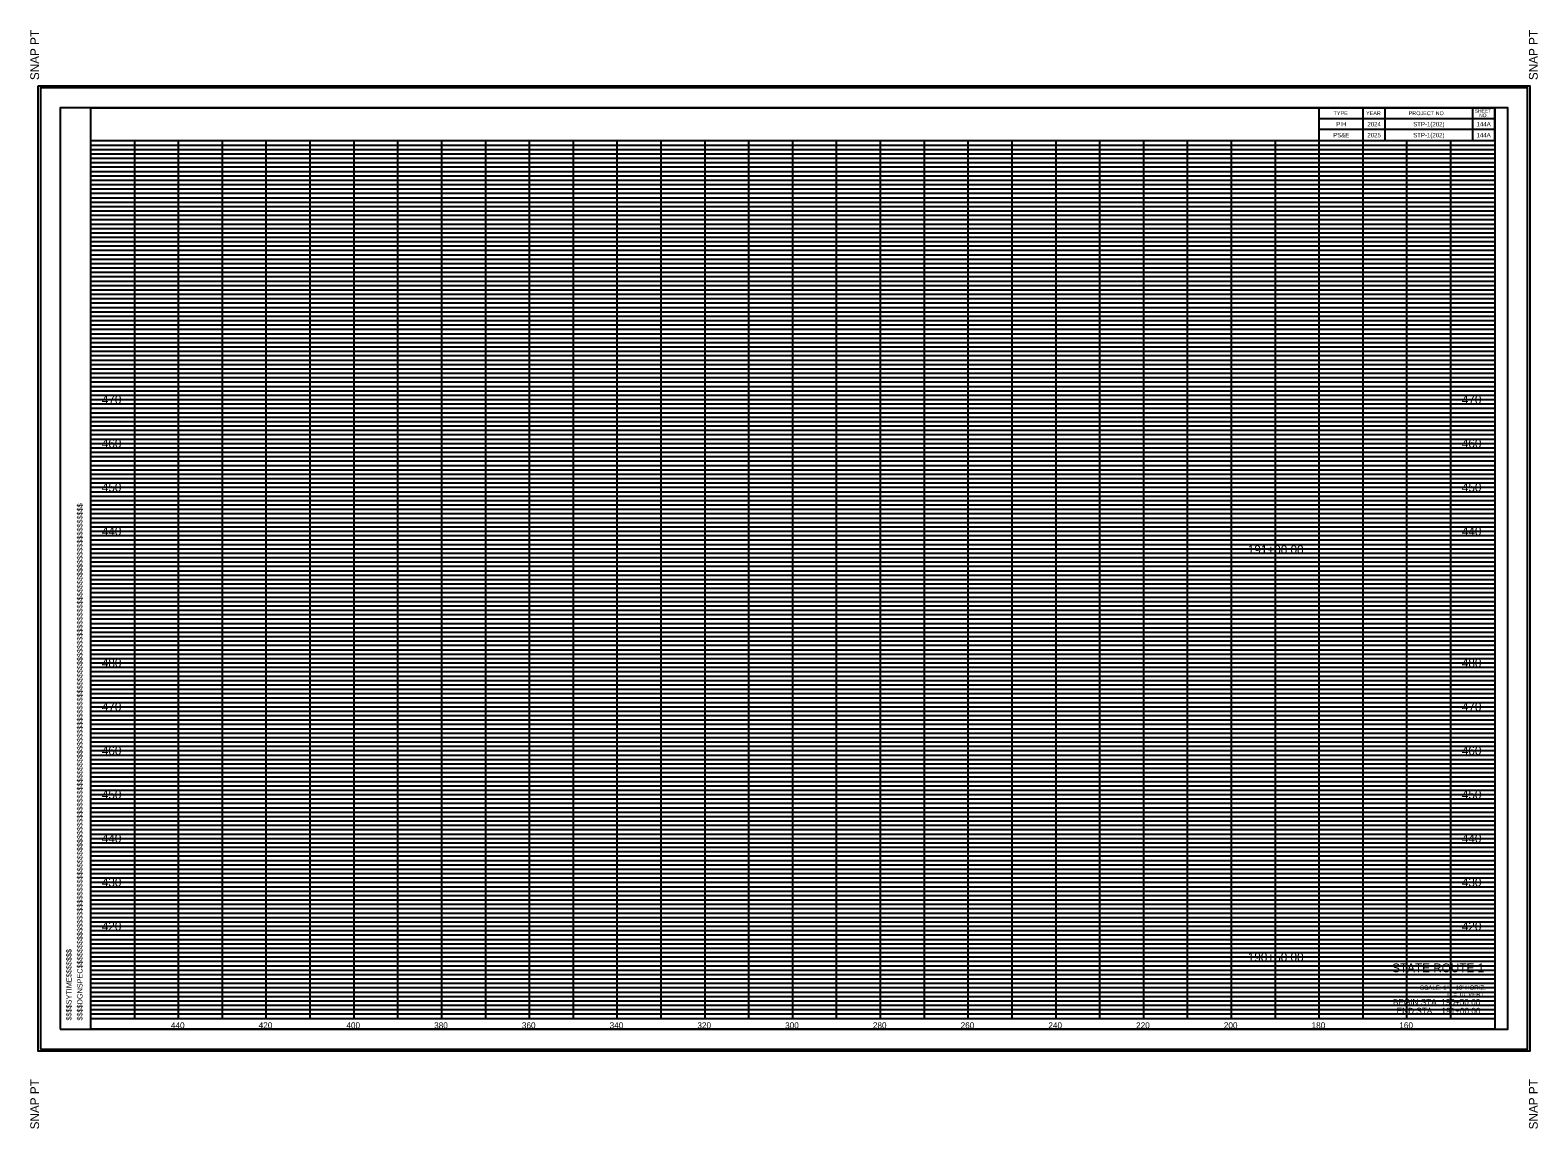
# Model space of a CAD drawing. Extents: x -200 to 23470, y -200 to 2389.
# Drawn here: x 6266.2 to 6609.8, y 1494.8 to 1745.2 of the extents above; entities that cross this region are included whole.
import ezdxf

# ---------------------------------------------------------------- set-up
doc = ezdxf.new("R2010")
doc.units = 0
for name, color, linetype in [('Default', 7, 'Continuous'), ('DESIGN - SCRATCH - User 1', 7, 'Continuous'), ('DESIGN - SHEET - Corner Text', 7, 'Continuous'), ('DESIGN - SHEET - Light Grid', 7, 'Continuous'), ('DESIGN - SHEET - Linework', 7, 'Continuous'), ('DESIGN - SHEET - Plot Shape', 7, 'Continuous'), ('SURVEY - CENTERLINE - Preliminary', 7, 'Continuous')]:
    doc.layers.add(name, color=color, linetype=linetype)

# ---------------------------------------------------------------- blocks, each defined once
blk = doc.blocks.new('XSTSHT')
at = {"layer": 'DESIGN - SCRATCH - User 1'}
for p, q in [((28.5, 20.375), (28.5, 20.375)), ((29.25, 20.375), (29.25, 20.375)), ((30.5, 20.375), (30.5, 20.375)), ((31.75, 20.375), (31.75, 20.375)), ((28.5, 20.125), (28.5, 20.125)), ((29.25, 20.125), (29.25, 20.125)), ((30.5, 20.125), (30.5, 20.125)), ((31.75, 20.125), (31.75, 20.125)), ((0, 0), (0, 0))]:
    blk.add_line(p, q, dxfattribs=at)
at = {"layer": 'DESIGN - SHEET - Light Grid'}
for p, q in [((0, 19.9), (32, 19.9)), ((0, 19.8), (32, 19.8)), ((0, 19.7), (32, 19.7)), ((0, 19.6), (32, 19.6)), ((0, 19.5), (32, 19.5)), ((0, 19.4), (32, 19.4)), ((0, 19.3), (32, 19.3)), ((0, 19.2), (32, 19.2)), ((0, 19.1), (32, 19.1)), ((0, 18.9), (32, 18.9)), ((0, 18.8), (32, 18.8)), ((0, 18.7), (32, 18.7)), ((0, 18.6), (32, 18.6)), ((0, 18.5), (32, 18.5)), ((0, 18.4), (32, 18.4)), ((0, 18.3), (32, 18.3)), ((0, 18.2), (32, 18.2)), ((0, 18.1), (32, 18.1)), ((0, 17.9), (32, 17.9)), ((0, 17.8), (32, 17.8)), ((0, 17.7), (32, 17.7)), ((0, 17.6), (32, 17.6)), ((0, 17.5), (32, 17.5)), ((0, 17.4), (32, 17.4)), ((0, 17.3), (32, 17.3)), ((0, 17.2), (32, 17.2)), ((0, 17.1), (32, 17.1)), ((0, 16.9), (32, 16.9)), ((0, 16.8), (32, 16.8)), ((0, 16.7), (32, 16.7)), ((0, 16.6), (32, 16.6)), ((0, 16.5), (32, 16.5)), ((0, 16.4), (32, 16.4)), ((0, 16.3), (32, 16.3)), ((0, 16.2), (32, 16.2)), ((0, 16.1), (32, 16.1)), ((0, 15.9), (32, 15.9)), ((0, 15.8), (32, 15.8)), ((0, 15.7), (32, 15.7)), ((0, 15.6), (32, 15.6)), ((0, 15.5), (32, 15.5)), ((0, 15.4), (32, 15.4)), ((0, 15.3), (32, 15.3)), ((0, 15.2), (32, 15.2)), ((0, 15.1), (32, 15.1)), ((0, 14.9), (32, 14.9)), ((0, 14.8), (32, 14.8)), ((0, 14.7), (32, 14.7)), ((0, 14.6), (32, 14.6)), ((0, 14.5), (32, 14.5)), ((0, 14.4), (32, 14.4)), ((0, 14.3), (32, 14.3)), ((0, 14.2), (32, 14.2)), ((0, 14.1), (32, 14.1)), ((0, 13.9), (32, 13.9)), ((0, 13.8), (32, 13.8)), ((0, 13.7), (32, 13.7)), ((0, 13.6), (32, 13.6)), ((0, 13.5), (32, 13.5)), ((0, 13.4), (32, 13.4)), ((0, 13.3), (32, 13.3)), ((0, 13.2), (32, 13.2)), ((0, 13.1), (32, 13.1)), ((0, 12.9), (32, 12.9)), ((0, 12.8), (32, 12.8)), ((0, 12.7), (32, 12.7)), ((0, 12.6), (32, 12.6)), ((0, 12.5), (32, 12.5)), ((0, 12.4), (32, 12.4)), ((0, 12.3), (32, 12.3)), ((0, 12.2), (32, 12.2)), ((0, 12.1), (32, 12.1)), ((0, 11.9), (32, 11.9)), ((0, 11.8), (32, 11.8)), ((0, 11.7), (32, 11.7)), ((0, 11.6), (32, 11.6)), ((0, 11.5), (32, 11.5)), ((0, 11.4), (32, 11.4)), ((0, 11.3), (32, 11.3)), ((0, 11.2), (32, 11.2)), ((0, 11.1), (32, 11.1)), ((0, 10.9), (32, 10.9)), ((0, 10.8), (32, 10.8)), ((0, 10.7), (32, 10.7)), ((0, 10.6), (32, 10.6)), ((0, 10.5), (32, 10.5)), ((0, 10.4), (32, 10.4)), ((0, 10.3), (32, 10.3)), ((0, 10.2), (32, 10.2)), ((0, 10.1), (32, 10.1)), ((0, 9.9), (32, 9.9)), ((0, 9.8), (32, 9.8)), ((0, 9.7), (32, 9.7)), ((0, 9.6), (32, 9.6)), ((0, 9.5), (32, 9.5)), ((0, 9.4), (32, 9.4)), ((0, 9.3), (32, 9.3)), ((0, 9.2), (32, 9.2)), ((0, 9.1), (32, 9.1)), ((0, 8.9), (32, 8.9)), ((0, 8.8), (32, 8.8)), ((0, 8.7), (32, 8.7)), ((0, 8.6), (32, 8.6)), ((0, 8.5), (32, 8.5)), ((0, 8.4), (32, 8.4)), ((0, 8.3), (32, 8.3)), ((0, 8.2), (32, 8.2)), ((0, 8.1), (32, 8.1)), ((0, 7.9), (32, 7.9)), ((0, 7.8), (32, 7.8)), ((0, 7.7), (32, 7.7)), ((0, 7.6), (32, 7.6)), ((0, 7.5), (32, 7.5)), ((0, 7.4), (32, 7.4)), ((0, 7.3), (32, 7.3)), ((0, 7.2), (32, 7.2)), ((0, 7.1), (32, 7.1)), ((0, 6.9), (32, 6.9)), ((0, 6.8), (32, 6.8)), ((0, 6.7), (32, 6.7)), ((0, 6.6), (32, 6.6)), ((0, 6.5), (32, 6.5)), ((0, 6.4), (32, 6.4)), ((0, 6.3), (32, 6.3)), ((0, 6.2), (32, 6.2)), ((0, 6.1), (32, 6.1)), ((0, 5.9), (32, 5.9)), ((0, 5.8), (32, 5.8)), ((0, 5.7), (32, 5.7)), ((0, 5.6), (32, 5.6)), ((0, 5.5), (32, 5.5)), ((0, 5.4), (32, 5.4)), ((0, 5.3), (32, 5.3)), ((0, 5.2), (32, 5.2)), ((0, 5.1), (32, 5.1)), ((0, 4.9), (32, 4.9)), ((0, 4.8), (32, 4.8)), ((0, 4.7), (32, 4.7)), ((0, 4.6), (32, 4.6)), ((0, 4.5), (32, 4.5)), ((0, 4.4), (32, 4.4)), ((0, 4.3), (32, 4.3)), ((0, 4.2), (32, 4.2)), ((0, 4.1), (32, 4.1)), ((0, 3.9), (32, 3.9)), ((0, 3.8), (32, 3.8)), ((0, 3.7), (32, 3.7)), ((0, 3.6), (32, 3.6)), ((0, 3.5), (32, 3.5)), ((0, 3.4), (32, 3.4)), ((0, 3.3), (32, 3.3)), ((0, 3.2), (32, 3.2)), ((0, 3.1), (32, 3.1)), ((0, 2.9), (32, 2.9)), ((0, 2.8), (32, 2.8)), ((0, 2.7), (32, 2.7)), ((0, 2.6), (32, 2.6)), ((0, 2.5), (32, 2.5)), ((0, 2.4), (32, 2.4)), ((0, 2.3), (32, 2.3)), ((0, 2.2), (32, 2.2)), ((0, 2.1), (32, 2.1)), ((0, 1.9), (32, 1.9)), ((0, 1.8), (32, 1.8)), ((0, 1.7), (32, 1.7)), ((0, 1.6), (32, 1.6)), ((0, 1.5), (32, 1.5)), ((0, 1.4), (32, 1.4)), ((0, 1.3), (32, 1.3)), ((0, 1.2), (32, 1.2)), ((0, 1.1), (32, 1.1)), ((0, 0.9), (32, 0.9)), ((0, 0.8), (32, 0.8)), ((0, 0.7), (32, 0.7)), ((0, 0.6), (32, 0.6)), ((0, 0.5), (32, 0.5)), ((0, 0.4), (32, 0.4)), ((0, 0.3), (32, 0.3)), ((0, 0.2), (32, 0.2)), ((0, 0.1), (32, 0.1))]:
    blk.add_line(p, q, dxfattribs=at)
at = {"layer": 'DESIGN - SHEET - Linework'}
for p, q in [((32, 20.75), (28, 20.75)), ((28, 20), (28, 20.75)), ((29, 20), (29, 20.75)), ((29.5, 20), (29.5, 20.75)), ((31.5, 20), (31.5, 20.75)), ((32, 20), (32, 20.75)), ((32, 20.5), (28, 20.5)), ((0, 20), (32, 20)), ((1, 0), (1, 20)), ((2, 0), (2, 20)), ((3, 0), (3, 20)), ((4, 0), (4, 20)), ((5, 0), (5, 20)), ((6, 0), (6, 20)), ((7, 0), (7, 20)), ((8, 0), (8, 20)), ((9, 0), (9, 20)), ((10, 0), (10, 20)), ((11, 0), (11, 20)), ((12, 0), (12, 20)), ((13, 0), (13, 20)), ((14, 0), (14, 20)), ((15, 0), (15, 20)), ((16, 0), (16, 20)), ((17, 0), (17, 20)), ((18, 0), (18, 20)), ((19, 0), (19, 20)), ((20, 0), (20, 20)), ((21, 0), (21, 20)), ((22, 0), (22, 20)), ((23, 0), (23, 20)), ((24, 0), (24, 20)), ((25, 0), (25, 20)), ((26, 0), (26, 20)), ((27, 0), (27, 20)), ((32, 20.25), (28, 20.25)), ((28, 0), (28, 20)), ((29, 0), (29, 20)), ((30, 0), (30, 20)), ((31, 0), (31, 20)), ((0, 19), (32, 19)), ((0, 18), (32, 18)), ((0, 17), (32, 17)), ((0, 16), (32, 16)), ((0, 15), (32, 15)), ((0, 14), (32, 14)), ((0, 13), (32, 13)), ((0, 12), (32, 12)), ((0, 11), (32, 11)), ((0, 10), (32, 10)), ((0, 9), (32, 9)), ((0, 8), (32, 8)), ((0, 7), (32, 7)), ((0, 6), (32, 6)), ((0, 5), (32, 5)), ((0, 4), (32, 4)), ((0, 3), (32, 3)), ((0, 2), (32, 2)), ((0, 1), (32, 1)), ((0, 0), (32, 0))]:
    blk.add_line(p, q, dxfattribs=at)
for points in [[(-1.2, 21.25), (32.8, 21.25), (32.8, -0.75), (-1.2, -0.75)], [(0, 20.75), (32, 20.75), (32, -0.25), (0, -0.25)]]:
    blk.add_lwpolyline(points, close=True, dxfattribs=at)
at = {"layer": 'DESIGN - SHEET - Corner Text'}
for s, height, p in [('  SNAP PT', 0.2, (-1.18, 21.23)), ('  SNAP PT', 0.2, (32.98, 21.23)), ('$$$$DGNSPEC$$$$$$$$$$$$$$$$$$$$$$$$$$$$$$$$$$$$$$$$$$$$$$$$$$$$$$$$$$$$$$$$$$$$$$$$$$$$$$$$$$$$$$$$$$$$$$$$$$$$$$$$$$$$$$$$$$$', 0.12, (-0.19, -0.05)), ('$$$$SYTIME$$$$$$$', 0.12, (-0.44, -0.05)), ('SNAP PT  ', 0.2, (-1.18, -2.53)), ('SNAP PT  ', 0.2, (32.98, -2.53))]:
    blk.add_text(s, height=height, rotation=90, dxfattribs=at).set_placement(p)
at = {"layer": 'DESIGN - SHEET - Light Grid'}
for s, height, p in [('TYPE', 0.09, (28.326, 20.58)), ('YEAR', 0.09, (29.066, 20.58)), ('PROJECT NO.', 0.09, (30.038, 20.58)), ('SHEET', 0.08, (31.547, 20.635)), ('NO.', 0.08, (31.647, 20.535))]:
    blk.add_text(s, height=height, dxfattribs=at).set_placement(p)

msp = doc.modelspace()

# ---------------------------------------------------------------- linework, layer by layer
at = {"layer": 'DESIGN - SHEET - Plot Shape'}
for points in [[(6268.5, 1513), (6607.5, 1513), (6607.5, 1732), (6268.5, 1732)], [(6273, 1517.5), (6603, 1517.5), (6603, 1727.5), (6273, 1727.5)]]:
    msp.add_lwpolyline(points, close=True, dxfattribs=at)

# ---------------------------------------------------------------- block references
at = {"layer": 'SURVEY - CENTERLINE - Preliminary', "xscale": 10, "yscale": 10}
msp.add_blockref('XSTSHT', (6280, 1520), dxfattribs=at)
msp.add_blockref('XSTSHT', (6280, 1520), dxfattribs=at)

# ---------------------------------------------------------------- texts
at = {"layer": 'Default'}
for s, height, p in [('     470     ', 2, (6278.79, 1660)), ('     470     ', 2, (6588.79, 1660)), ('     460     ', 2, (6278.79, 1650)), ('     460     ', 2, (6588.79, 1650)), ('     450     ', 2, (6278.79, 1640)), ('     450     ', 2, (6588.79, 1640)), ('     440     ', 2, (6278.79, 1630)), ('     440     ', 2, (6588.79, 1630)), ('     191+00.00     ', 2, (6540, 1625.79)), ('     480     ', 2, (6278.79, 1600)), ('     480     ', 2, (6588.79, 1600)), ('     470     ', 2, (6278.79, 1590)), ('     470     ', 2, (6588.79, 1590)), ('     460     ', 2, (6278.79, 1580)), ('     460     ', 2, (6588.79, 1580)), ('     450     ', 2, (6278.79, 1570)), ('     450     ', 2, (6588.79, 1570)), ('     440     ', 2, (6278.79, 1560)), ('     440     ', 2, (6588.79, 1560)), ('     430     ', 2, (6278.79, 1550)), ('     430     ', 2, (6588.79, 1550)), ('     420     ', 2, (6278.79, 1540)), ('     420     ', 2, (6588.79, 1540)), ('     190+50.00     ', 2, (6540, 1532.94)), ('     440     ', 1.4, (6295.65, 1517.7)), ('     420     ', 1.4, (6315.65, 1517.7)), ('     400     ', 1.4, (6335.65, 1517.7)), ('     380     ', 1.4, (6355.65, 1517.7)), ('     360     ', 1.4, (6375.65, 1517.7)), ('     340     ', 1.4, (6395.65, 1517.7)), ('     320     ', 1.4, (6415.65, 1517.7)), ('     300     ', 1.4, (6435.65, 1517.7)), ('     280     ', 1.4, (6455.65, 1517.7)), ('     260     ', 1.4, (6475.65, 1517.7)), ('     240     ', 1.4, (6495.65, 1517.7)), ('     220     ', 1.4, (6515.65, 1517.7)), ('     200     ', 1.4, (6535.65, 1517.7)), ('     180     ', 1.4, (6555.65, 1517.7)), ('     160     ', 1.4, (6575.65, 1517.7))]:
    msp.add_text(s, height=height, dxfattribs=at).set_placement(p)
at = {"layer": 'DESIGN - SHEET - Corner Text'}
for s, height, p in [('PS&E', 1, (6563.17, 1720.75)), ('PIH', 1, (6563.89, 1723.25)), ('2025', 1, (6570.97, 1720.75)), ('2024', 1, (6570.98, 1723.25)), ('STP-1(202)', 1, (6581.42, 1723.25)), ('STP-1(202)', 1, (6581.42, 1720.75)), ('144A', 1, (6595.87, 1723.25)), ('144A', 1, (6595.87, 1720.75)), ('STATE ROUTE 1', 2, (6576.62, 1530.5)), ('SCALE: 1" = 10\' HORIZ.', 1, (6582.96, 1526.5)), ('1" = 10\' VERT.', 1, (6588.93, 1525)), ('BEGIN STA. 190+50.00', 1.4, (6576.78, 1523)), ('END STA.   191+00.00', 1.4, (6577.65, 1521))]:
    msp.add_text(s, height=height, dxfattribs=at).set_placement(p)

doc.saveas('drawing.dxf')
